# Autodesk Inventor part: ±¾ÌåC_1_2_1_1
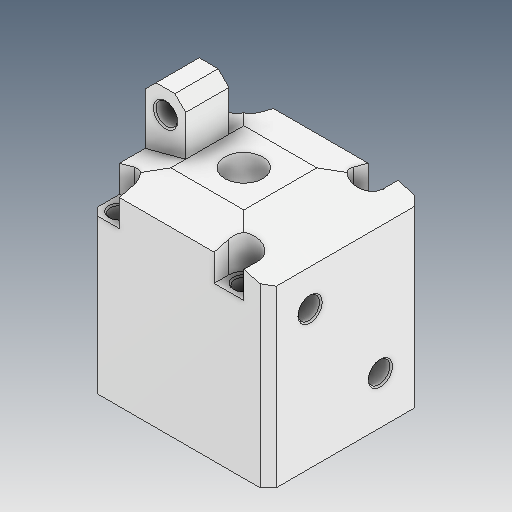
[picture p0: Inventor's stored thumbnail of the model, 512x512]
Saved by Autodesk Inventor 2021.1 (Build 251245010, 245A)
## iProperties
Created: 2021-05
Part Number: ±¾ÌåC_1_2_1_1
Material: Ogólny
Document SubType Name: Modeling
Designer: user
Density: 1 g/cm^3
Appearance: Domyślna
Author: user
Revision Number: ÈÎºÎ
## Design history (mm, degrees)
feature "ÊäÈë1"
node "Bryła1"
